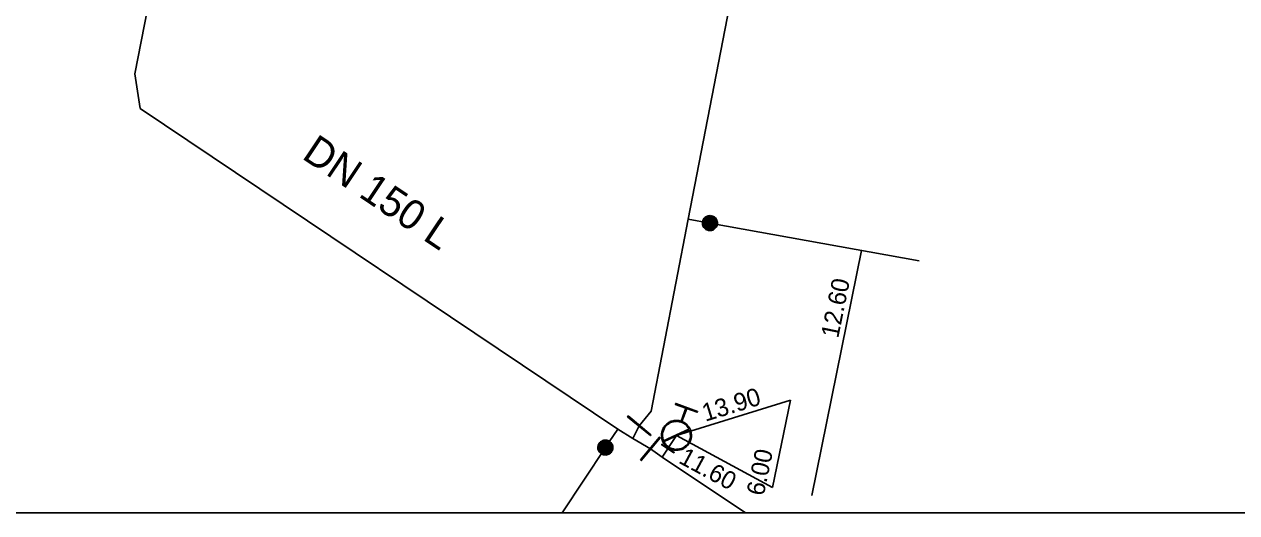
# Model space of a CAD drawing. Extents: x -820257 to -819974, y -1070894 to -1070484.
# Drawn here: x -820139 to -820057.3, y -1070893.9 to -1070861 of the extents above; entities that cross this region are included whole.
import ezdxf

# ---------------------------------------------------------------- set-up
doc = ezdxf.new("R2010")
doc.units = 0
for name, color, linetype in [('Default', 7, 'Continuous'), ('Hyd-odbočka', 7, 'Continuous'), ('Hyd-šoupě', 7, 'Continuous'), ('Hydrant', 7, 'Continuous'), ('Oměrka vodovodu', 7, 'Continuous'), ('Oměrka-text', 7, 'Continuous'), ('Přípojka vodovodu', 7, 'Continuous'), ('Přípojkový uzávěr', 7, 'Continuous'), ('Roz-řad', 7, 'Continuous'), ('Roz-řad-popis základní', 7, 'Continuous'), ('Řad-šoupě', 7, 'Continuous')]:
    doc.layers.add(name, color=color, linetype=linetype)

msp = doc.modelspace()

# ---------------------------------------------------------------- linework, layer by layer
at = {"layer": 'Default'}
msp.add_line((-820256.81, -1070893.932), (-819975.603, -1070893.932), dxfattribs=at)
at = {"layer": 'Hyd-odbočka'}
msp.add_line((-820095.994, -1070890.18), (-820095.035, -1070888.718), dxfattribs=at)
at = {"layer": 'Hyd-šoupě'}
msp.add_lwpolyline([(-820096.025, -1070889.316), (-820095.189, -1070889.865), (-820095.206, -1070889.891), (-820096.042, -1070889.342), (-820096.025, -1070889.316)], dxfattribs=at)
at = {"layer": 'Hydrant'}
for points in [[(-820094.72, -1070887.768), (-820094.398, -1070886.887), (-820095.102, -1070886.63), (-820095.081, -1070886.571), (-820093.614, -1070887.108), (-820093.635, -1070887.167), (-820094.339, -1070886.909), (-820094.662, -1070887.789)], [(-820095.899, -1070889.085), (-820094.196, -1070888.295)], [(-820094.17, -1070888.35), (-820095.874, -1070889.142)]]:
    msp.add_lwpolyline(points, dxfattribs=at)
for points in [[(-820094.662, -1070887.789), (-820094.442, -1070887.878), (-820094.273, -1070888.069), (-820094.094, -1070888.272), (-820094.05, -1070888.544), (-820094.006, -1070888.816), (-820094.096, -1070889.061), (-820094.185, -1070889.305), (-820094.391, -1070889.484), (-820094.596, -1070889.662), (-820094.865, -1070889.704), (-820095.134, -1070889.746), (-820095.378, -1070889.657), (-820095.622, -1070889.567), (-820095.801, -1070889.362), (-820095.979, -1070889.156), (-820096.021, -1070888.887), (-820096.063, -1070888.618), (-820095.974, -1070888.374), (-820095.884, -1070888.128), (-820095.675, -1070887.949), (-820095.466, -1070887.77), (-820095.197, -1070887.73), (-820094.947, -1070887.693), (-820094.72, -1070887.768)], [(-820094.196, -1070888.295), (-820094.246, -1070888.195), (-820094.321, -1070888.109), (-820094.491, -1070887.918), (-820094.712, -1070887.837), (-820094.934, -1070887.756), (-820095.187, -1070887.793), (-820095.439, -1070887.829), (-820095.635, -1070887.997), (-820095.83, -1070888.164), (-820095.915, -1070888.395), (-820095.999, -1070888.625), (-820095.958, -1070888.877), (-820095.942, -1070888.987), (-820095.899, -1070889.085)], [(-820095.874, -1070889.142), (-820095.826, -1070889.237), (-820095.752, -1070889.32), (-820095.586, -1070889.514), (-820095.357, -1070889.598), (-820095.128, -1070889.682), (-820094.875, -1070889.642), (-820094.622, -1070889.603), (-820094.43, -1070889.436), (-820094.238, -1070889.269), (-820094.154, -1070889.04), (-820094.07, -1070888.809), (-820094.112, -1070888.554), (-820094.13, -1070888.445), (-820094.17, -1070888.35)]]:
    msp.add_open_spline(points, degree=3, dxfattribs=at)
at = {"layer": 'Oměrka vodovodu'}
for p, q in [((-820082.567, -1070876.261), (-820085.918, -1070892.772)), ((-820095.035, -1070888.718), (-820087.354, -1070886.349)), ((-820087.354, -1070886.349), (-820088.575, -1070892.223)), ((-820095.035, -1070888.718), (-820088.575, -1070892.223))]:
    msp.add_line(p, q, dxfattribs=at)
at = {"layer": 'Přípojka vodovodu'}
for points in [[(-820094.255, -1070874.154), (-820092.779, -1070874.42), (-820078.675, -1070876.962)], [(-820098.993, -1070888.291), (-820099.573, -1070889.163), (-820099.823, -1070889.541), (-820102.729, -1070893.932)]]:
    msp.add_lwpolyline(points, dxfattribs=at)
at = {"layer": 'Přípojkový uzávěr'}
for points in [[(-820092.691, -1070873.928), (-820092.567, -1070873.951), (-820092.461, -1070874.035), (-820092.354, -1070874.12), (-820092.309, -1070874.251), (-820092.264, -1070874.381), (-820092.287, -1070874.51), (-820092.31, -1070874.638), (-820092.396, -1070874.743), (-820092.482, -1070874.848), (-820092.611, -1070874.892), (-820092.74, -1070874.936), (-820092.868, -1070874.913), (-820092.996, -1070874.89), (-820093.101, -1070874.804), (-820093.207, -1070874.718), (-820093.251, -1070874.589), (-820093.294, -1070874.46), (-820093.271, -1070874.332), (-820093.248, -1070874.204), (-820093.161, -1070874.097), (-820093.073, -1070873.991), (-820092.944, -1070873.948), (-820092.815, -1070873.906), (-820092.691, -1070873.928)], [(-820092.699, -1070873.975), (-820092.812, -1070873.954), (-820092.929, -1070873.993), (-820093.046, -1070874.031), (-820093.125, -1070874.127), (-820093.204, -1070874.224), (-820093.225, -1070874.341), (-820093.246, -1070874.457), (-820093.207, -1070874.573), (-820093.167, -1070874.69), (-820093.071, -1070874.768), (-820092.975, -1070874.846), (-820092.86, -1070874.866), (-820092.744, -1070874.887), (-820092.627, -1070874.848), (-820092.51, -1070874.808), (-820092.432, -1070874.713), (-820092.354, -1070874.617), (-820092.333, -1070874.501), (-820092.312, -1070874.385), (-820092.354, -1070874.266), (-820092.395, -1070874.148), (-820092.491, -1070874.071), (-820092.587, -1070873.995), (-820092.699, -1070873.975)], [(-820092.705, -1070874.008), (-820092.601, -1070874.027), (-820092.512, -1070874.098), (-820092.424, -1070874.169), (-820092.386, -1070874.278), (-820092.348, -1070874.387), (-820092.367, -1070874.495), (-820092.386, -1070874.603), (-820092.458, -1070874.691), (-820092.53, -1070874.779), (-820092.638, -1070874.816), (-820092.746, -1070874.852), (-820092.854, -1070874.833), (-820092.961, -1070874.814), (-820093.049, -1070874.742), (-820093.138, -1070874.669), (-820093.175, -1070874.562), (-820093.211, -1070874.454), (-820093.192, -1070874.347), (-820093.172, -1070874.239), (-820093.099, -1070874.149), (-820093.026, -1070874.06), (-820092.918, -1070874.025), (-820092.809, -1070873.99), (-820092.705, -1070874.008)], [(-820092.714, -1070874.051), (-820092.867, -1070874.024), (-820092.994, -1070874.112), (-820093.121, -1070874.201), (-820093.148, -1070874.355), (-820093.176, -1070874.507), (-820093.087, -1070874.635), (-820092.999, -1070874.762), (-820092.847, -1070874.789), (-820092.693, -1070874.817), (-820092.565, -1070874.729), (-820092.438, -1070874.64), (-820092.41, -1070874.488), (-820092.383, -1070874.334), (-820092.471, -1070874.207), (-820092.558, -1070874.079), (-820092.714, -1070874.051)], [(-820092.722, -1070874.097), (-820092.587, -1070874.121), (-820092.51, -1070874.232), (-820092.433, -1070874.344), (-820092.457, -1070874.478), (-820092.481, -1070874.612), (-820092.593, -1070874.689), (-820092.704, -1070874.767), (-820092.838, -1070874.742), (-820092.973, -1070874.718), (-820093.05, -1070874.607), (-820093.127, -1070874.495), (-820093.103, -1070874.361), (-820093.079, -1070874.227), (-820092.968, -1070874.15), (-820092.856, -1070874.072), (-820092.722, -1070874.097)], [(-820092.729, -1070874.135), (-820092.847, -1070874.114), (-820092.945, -1070874.182), (-820093.043, -1070874.251), (-820093.064, -1070874.368), (-820093.085, -1070874.486), (-820093.017, -1070874.584), (-820092.949, -1070874.682), (-820092.831, -1070874.703), (-820092.713, -1070874.725), (-820092.615, -1070874.657), (-820092.517, -1070874.588), (-820092.496, -1070874.471), (-820092.475, -1070874.353), (-820092.542, -1070874.255), (-820092.61, -1070874.157), (-820092.729, -1070874.135)], [(-820092.735, -1070874.174), (-820092.632, -1070874.193), (-820092.573, -1070874.278), (-820092.515, -1070874.363), (-820092.533, -1070874.465), (-820092.552, -1070874.567), (-820092.637, -1070874.626), (-820092.722, -1070874.685), (-820092.824, -1070874.667), (-820092.925, -1070874.648), (-820092.985, -1070874.563), (-820093.044, -1070874.479), (-820093.025, -1070874.377), (-820093.007, -1070874.274), (-820092.923, -1070874.215), (-820092.838, -1070874.156), (-820092.735, -1070874.174)], [(-820092.744, -1070874.22), (-820092.827, -1070874.205), (-820092.896, -1070874.253), (-820092.965, -1070874.301), (-820092.98, -1070874.384), (-820092.995, -1070874.467), (-820092.947, -1070874.536), (-820092.899, -1070874.605), (-820092.816, -1070874.62), (-820092.733, -1070874.635), (-820092.664, -1070874.587), (-820092.595, -1070874.539), (-820092.58, -1070874.456), (-820092.565, -1070874.373), (-820092.613, -1070874.304), (-820092.66, -1070874.235), (-820092.744, -1070874.22)], [(-820092.75, -1070874.254), (-820092.681, -1070874.267), (-820092.641, -1070874.324), (-820092.601, -1070874.381), (-820092.614, -1070874.45), (-820092.626, -1070874.519), (-820092.684, -1070874.559), (-820092.741, -1070874.598), (-820092.81, -1070874.586), (-820092.879, -1070874.573), (-820092.918, -1070874.516), (-820092.958, -1070874.459), (-820092.945, -1070874.39), (-820092.933, -1070874.321), (-820092.876, -1070874.281), (-820092.819, -1070874.242), (-820092.75, -1070874.254)], [(-820092.758, -1070874.298), (-820092.808, -1070874.288), (-820092.851, -1070874.318), (-820092.893, -1070874.348), (-820092.902, -1070874.398), (-820092.911, -1070874.449), (-820092.882, -1070874.492), (-820092.852, -1070874.534), (-820092.802, -1070874.544), (-820092.75, -1070874.553), (-820092.708, -1070874.523), (-820092.665, -1070874.494), (-820092.656, -1070874.443), (-820092.647, -1070874.392), (-820092.676, -1070874.349), (-820092.706, -1070874.307), (-820092.758, -1070874.298)], [(-820092.766, -1070874.344), (-820092.733, -1070874.35), (-820092.715, -1070874.376), (-820092.697, -1070874.402), (-820092.703, -1070874.434), (-820092.709, -1070874.466), (-820092.735, -1070874.485), (-820092.761, -1070874.503), (-820092.794, -1070874.497), (-820092.825, -1070874.492), (-820092.844, -1070874.465), (-820092.862, -1070874.438), (-820092.857, -1070874.407), (-820092.851, -1070874.374), (-820092.824, -1070874.356), (-820092.798, -1070874.338), (-820092.766, -1070874.344)], [(-820092.771, -1070874.374), (-820092.791, -1070874.371), (-820092.806, -1070874.382), (-820092.822, -1070874.393), (-820092.826, -1070874.412), (-820092.829, -1070874.431), (-820092.818, -1070874.447), (-820092.807, -1070874.463), (-820092.788, -1070874.467), (-820092.768, -1070874.47), (-820092.753, -1070874.459), (-820092.737, -1070874.448), (-820092.734, -1070874.429), (-820092.73, -1070874.409), (-820092.741, -1070874.394), (-820092.752, -1070874.378), (-820092.771, -1070874.374)], [(-820100.24, -1070889.266), (-820100.171, -1070889.161), (-820100.051, -1070889.096), (-820099.931, -1070889.032), (-820099.794, -1070889.042), (-820099.656, -1070889.052), (-820099.547, -1070889.124), (-820099.438, -1070889.196), (-820099.376, -1070889.317), (-820099.313, -1070889.437), (-820099.324, -1070889.573), (-820099.334, -1070889.709), (-820099.406, -1070889.817), (-820099.478, -1070889.925), (-820099.598, -1070889.988), (-820099.719, -1070890.051), (-820099.855, -1070890.041), (-820099.99, -1070890.03), (-820100.099, -1070889.958), (-820100.208, -1070889.886), (-820100.271, -1070889.764), (-820100.334, -1070889.641), (-820100.322, -1070889.506), (-820100.31, -1070889.371), (-820100.24, -1070889.266)], [(-820100.201, -1070889.291), (-820100.264, -1070889.387), (-820100.275, -1070889.509), (-820100.287, -1070889.632), (-820100.229, -1070889.743), (-820100.172, -1070889.854), (-820100.073, -1070889.919), (-820099.975, -1070889.984), (-820099.852, -1070889.994), (-820099.729, -1070890.004), (-820099.62, -1070889.946), (-820099.51, -1070889.889), (-820099.445, -1070889.792), (-820099.38, -1070889.693), (-820099.37, -1070889.57), (-820099.361, -1070889.447), (-820099.418, -1070889.338), (-820099.474, -1070889.228), (-820099.573, -1070889.163), (-820099.672, -1070889.098), (-820099.797, -1070889.089), (-820099.921, -1070889.08), (-820100.03, -1070889.138), (-820100.138, -1070889.196), (-820100.201, -1070889.291)], [(-820100.173, -1070889.31), (-820100.114, -1070889.222), (-820100.014, -1070889.168), (-820099.914, -1070889.115), (-820099.799, -1070889.123), (-820099.683, -1070889.131), (-820099.591, -1070889.192), (-820099.501, -1070889.252), (-820099.448, -1070889.353), (-820099.395, -1070889.454), (-820099.404, -1070889.568), (-820099.414, -1070889.681), (-820099.474, -1070889.773), (-820099.534, -1070889.863), (-820099.635, -1070889.916), (-820099.736, -1070889.969), (-820099.85, -1070889.96), (-820099.963, -1070889.951), (-820100.054, -1070889.891), (-820100.145, -1070889.83), (-820100.199, -1070889.728), (-820100.252, -1070889.625), (-820100.241, -1070889.512), (-820100.231, -1070889.398), (-820100.173, -1070889.31)], [(-820100.136, -1070889.335), (-820100.223, -1070889.465), (-820100.191, -1070889.617), (-820100.159, -1070889.768), (-820100.03, -1070889.854), (-820099.9, -1070889.94), (-820099.748, -1070889.909), (-820099.596, -1070889.878), (-820099.511, -1070889.749), (-820099.425, -1070889.619), (-820099.455, -1070889.466), (-820099.486, -1070889.314), (-820099.616, -1070889.229), (-820099.746, -1070889.143), (-820099.897, -1070889.173), (-820100.049, -1070889.203), (-820100.136, -1070889.335)], [(-820100.098, -1070889.36), (-820100.022, -1070889.246), (-820099.89, -1070889.219), (-820099.757, -1070889.193), (-820099.643, -1070889.268), (-820099.53, -1070889.343), (-820099.503, -1070889.476), (-820099.476, -1070889.609), (-820099.551, -1070889.722), (-820099.626, -1070889.836), (-820099.759, -1070889.863), (-820099.892, -1070889.89), (-820100.005, -1070889.815), (-820100.119, -1070889.74), (-820100.146, -1070889.607), (-820100.173, -1070889.474), (-820100.098, -1070889.36)], [(-820100.065, -1070889.382), (-820100.131, -1070889.482), (-820100.107, -1070889.599), (-820100.083, -1070889.716), (-820099.984, -1070889.782), (-820099.884, -1070889.848), (-820099.767, -1070889.824), (-820099.65, -1070889.801), (-820099.584, -1070889.701), (-820099.518, -1070889.601), (-820099.542, -1070889.484), (-820099.565, -1070889.367), (-820099.665, -1070889.301), (-820099.765, -1070889.235), (-820099.882, -1070889.258), (-820099.999, -1070889.282), (-820100.065, -1070889.382)], [(-820100.032, -1070889.404), (-820099.974, -1070889.316), (-820099.873, -1070889.296), (-820099.771, -1070889.275), (-820099.685, -1070889.333), (-820099.598, -1070889.39), (-820099.578, -1070889.491), (-820099.557, -1070889.593), (-820099.615, -1070889.679), (-820099.672, -1070889.765), (-820099.773, -1070889.786), (-820099.874, -1070889.807), (-820099.961, -1070889.75), (-820100.047, -1070889.692), (-820100.068, -1070889.592), (-820100.089, -1070889.491), (-820100.032, -1070889.404)], [(-820099.993, -1070889.429), (-820100.04, -1070889.5), (-820100.023, -1070889.582), (-820100.006, -1070889.664), (-820099.936, -1070889.711), (-820099.865, -1070889.757), (-820099.783, -1070889.741), (-820099.701, -1070889.724), (-820099.654, -1070889.653), (-820099.608, -1070889.583), (-820099.625, -1070889.501), (-820099.641, -1070889.418), (-820099.712, -1070889.372), (-820099.782, -1070889.325), (-820099.864, -1070889.342), (-820099.947, -1070889.359), (-820099.993, -1070889.429)], [(-820099.964, -1070889.448), (-820099.925, -1070889.39), (-820099.857, -1070889.376), (-820099.789, -1070889.362), (-820099.731, -1070889.401), (-820099.672, -1070889.44), (-820099.658, -1070889.508), (-820099.645, -1070889.576), (-820099.683, -1070889.634), (-820099.722, -1070889.693), (-820099.79, -1070889.707), (-820099.858, -1070889.721), (-820099.917, -1070889.682), (-820099.975, -1070889.643), (-820099.989, -1070889.575), (-820100.003, -1070889.507), (-820099.964, -1070889.448)], [(-820099.928, -1070889.473), (-820099.956, -1070889.516), (-820099.946, -1070889.566), (-820099.935, -1070889.617), (-820099.892, -1070889.645), (-820099.849, -1070889.674), (-820099.798, -1070889.664), (-820099.747, -1070889.653), (-820099.719, -1070889.61), (-820099.69, -1070889.567), (-820099.701, -1070889.516), (-820099.711, -1070889.465), (-820099.754, -1070889.437), (-820099.797, -1070889.408), (-820099.848, -1070889.418), (-820099.898, -1070889.429), (-820099.928, -1070889.473)], [(-820099.888, -1070889.498), (-820099.87, -1070889.471), (-820099.839, -1070889.464), (-820099.808, -1070889.458), (-820099.78, -1070889.476), (-820099.753, -1070889.494), (-820099.747, -1070889.526), (-820099.74, -1070889.557), (-820099.758, -1070889.585), (-820099.776, -1070889.612), (-820099.808, -1070889.618), (-820099.84, -1070889.624), (-820099.866, -1070889.607), (-820099.894, -1070889.588), (-820099.9, -1070889.557), (-820099.906, -1070889.525), (-820099.888, -1070889.498)], [(-820099.862, -1070889.516), (-820099.873, -1070889.532), (-820099.87, -1070889.551), (-820099.866, -1070889.57), (-820099.849, -1070889.581), (-820099.833, -1070889.591), (-820099.814, -1070889.588), (-820099.795, -1070889.584), (-820099.784, -1070889.567), (-820099.773, -1070889.551), (-820099.777, -1070889.532), (-820099.781, -1070889.513), (-820099.797, -1070889.502), (-820099.814, -1070889.491), (-820099.833, -1070889.495), (-820099.851, -1070889.499), (-820099.862, -1070889.516)]]:
    msp.add_open_spline(points, degree=3, dxfattribs=at)
at = {"layer": 'Roz-řad'}
for p, q in [((-820097.541, -1070888.076), (-820097.968, -1070888.921)), ((-820097.968, -1070888.921), (-820096.789, -1070889.625)), ((-820096.789, -1070889.625), (-820095.994, -1070890.18)), ((-820095.994, -1070890.18), (-820090.373, -1070893.932))]:
    msp.add_line(p, q, dxfattribs=at)
for points in [[(-820083.25, -1070815.478), (-820088.414, -1070844.049), (-820094.255, -1070874.154), (-820096.732, -1070887.1), (-820097.541, -1070888.076)], [(-820128.743, -1070850.133), (-820131.517, -1070864.357), (-820131.167, -1070866.699), (-820098.993, -1070888.291), (-820097.968, -1070888.921)]]:
    msp.add_lwpolyline(points, dxfattribs=at)
at = {"layer": 'Řad-šoupě'}
for points in [[(-820098.29, -1070887.413), (-820096.751, -1070888.689), (-820096.791, -1070888.737), (-820098.33, -1070887.461), (-820098.29, -1070887.413)], [(-820097.45, -1070890.374), (-820096.174, -1070888.835), (-820096.126, -1070888.875), (-820097.402, -1070890.414), (-820097.45, -1070890.374)]]:
    msp.add_lwpolyline(points, dxfattribs=at)

# ---------------------------------------------------------------- texts
at = {"layer": 'Oměrka-text'}
for s, rotation, p in [('12.60', 78.52736, (-820084.139, -1070882.219)), ('13.90', 17.14101, (-820093.092, -1070887.804)), ('11.60', 331.5171, (-820094.956, -1070890.537)), (' 6.00', 78.25744, (-820089.248, -1070893.279))]:
    msp.add_text(s, height=1.2, rotation=rotation, dxfattribs=at).set_placement(p)
at = {"layer": 'Roz-řad-popis základní'}
msp.add_text('DN 150 L', height=2, rotation=326.1344, dxfattribs=at).set_placement((-820120.343, -1070870.025))

doc.saveas('drawing.dxf')
